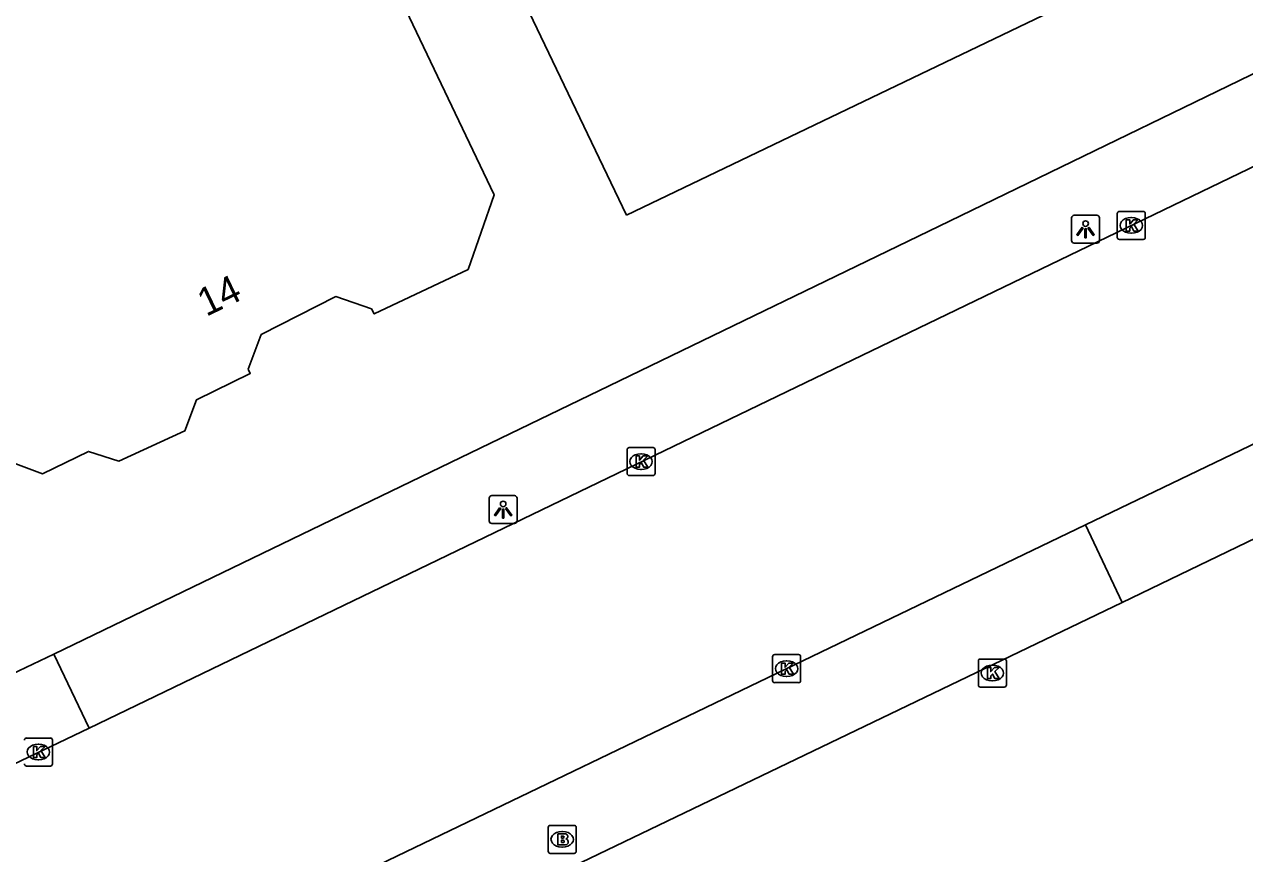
# Model space of a CAD drawing. Extents: x 157692 to 159670, y 381454 to 383289.
# Drawn here: x 158074.32 to 158117.92, y 381667.75 to 381697.36 of the extents above; entities that cross this region are included whole.
import ezdxf

# ---------------------------------------------------------------- set-up
doc = ezdxf.new("R2010")
doc.units = 0
for name, color, linetype in [('IMGEO_Brandkraan', 7, 'Continuous'), ('IMGEO_Kolk', 7, 'Continuous'), ('IMGEO_Lichtpunt', 7, 'Continuous'), ('IMGEO_Pand', 7, 'Continuous'), ('IMGEO_Pand_nummerreeks', 7, 'Continuous'), ('IMGEO_Rijbaan_lokaal_gesloten', 7, 'Continuous'), ('IMGEO_Voetpad_open', 7, 'Continuous')]:
    doc.layers.add(name, color=color, linetype=linetype)

msp = doc.modelspace()

# ---------------------------------------------------------------- linework, layer by layer
at = {"layer": 'IMGEO_Brandkraan'}
for p, q in [((158093.036, 381667.829), (158093.036, 381668.681)), ((158093.111, 381668.755), (158093.963, 381668.755)), ((158094.037, 381668.681), (158094.037, 381667.829)), ((158093.524, 381668.535), (158093.549, 381668.535)), ((158093.963, 381667.755), (158093.111, 381667.755)), ((158093.547, 381667.975), (158093.522, 381667.975))]:
    msp.add_line(p, q, dxfattribs=at)
for points in [[(158093.036, 381667.829), (158093.036, 381668.681)], [(158093.111, 381668.755), (158093.963, 381668.755)], [(158094.037, 381668.681), (158094.037, 381667.829)], [(158093.384, 381668.455), (158093.384, 381668.055), (158093.597, 381668.055)], [(158093.615, 381668.455), (158093.384, 381668.455)], [(158093.563, 381668.374), (158093.509, 381668.374), (158093.509, 381668.298)], [(158093.509, 381668.298), (158093.562, 381668.298)], [(158093.571, 381668.222), (158093.509, 381668.222), (158093.509, 381668.141)], [(158093.509, 381668.141), (158093.571, 381668.141)], [(158093.963, 381667.755), (158093.111, 381667.755)]]:
    msp.add_lwpolyline(points, dxfattribs=at)
for centre, radius, start, end in [((158093.113, 381668.679), 0.0765, 91.552, 178.448), ((158093.113, 381668.679), 0.0765, 91.552, 178.448), ((158093.961, 381668.679), 0.0765, 1.552, 88.448), ((158093.961, 381668.679), 0.0765, 1.552, 88.448), ((158093.564, 381668.336), 0.0379, 267.8285, 90.9355), ((158093.572, 381668.181), 0.0404, 269.8759, 90.5077), ((158093.619, 381668.31), 0.145, 59.4692, 91.5367), ((158093.644, 381668.357), 0.0922, 285.5137, 58.1501), ((158093.649, 381668.165), 0.105, 301.3115, 78.989), ((158093.113, 381667.831), 0.0765, 181.552, 268.448), ((158093.113, 381667.831), 0.0765, 181.552, 268.448), ((158093.603, 381668.306), 0.251, 268.6676, 293.5347), ((158093.961, 381667.831), 0.0765, 271.552, 358.448), ((158093.961, 381667.831), 0.0765, 271.552, 358.448)]:
    msp.add_arc(centre, radius, start, end, dxfattribs=at)
for centre, major_axis, ratio, start_param, end_param in [((158093.523, 381668.255), (-0.387, 0.002), 0.722429, 4.712389, 7.853982), ((158093.548, 381668.255), (-0.39, 0.002), 0.717154, 1.570796, 4.712389)]:
    msp.add_ellipse(centre, major_axis=major_axis, ratio=ratio, start_param=start_param, end_param=end_param, dxfattribs=at)
at = {"layer": 'IMGEO_Kolk'}
for p, q in [((158113.367, 381689.758), (158113.367, 381690.61)), ((158113.442, 381690.684), (158114.294, 381690.684)), ((158113.855, 381690.464), (158113.88, 381690.464)), ((158114.368, 381690.61), (158114.368, 381689.758)), ((158113.878, 381689.904), (158113.853, 381689.904)), ((158114.294, 381689.684), (158113.442, 381689.684)), ((158095.854, 381681.323), (158095.854, 381682.175)), ((158095.929, 381682.249), (158096.781, 381682.249)), ((158096.855, 381682.175), (158096.855, 381681.323)), ((158096.342, 381682.029), (158096.367, 381682.029)), ((158096.781, 381681.249), (158095.929, 381681.249)), ((158096.365, 381681.469), (158096.34, 381681.469)), ((158101.054, 381673.926), (158101.054, 381674.778)), ((158101.129, 381674.852), (158101.981, 381674.852)), ((158102.055, 381674.778), (158102.055, 381673.926)), ((158108.479, 381674.696), (158109.331, 381674.696)), ((158101.542, 381674.632), (158101.567, 381674.632)), ((158108.404, 381673.77), (158108.404, 381674.622)), ((158108.892, 381674.476), (158108.917, 381674.476)), ((158109.405, 381674.622), (158109.405, 381673.77)), ((158101.981, 381673.852), (158101.129, 381673.852)), ((158101.565, 381674.072), (158101.54, 381674.072)), ((158108.915, 381673.916), (158108.89, 381673.916)), ((158109.331, 381673.696), (158108.479, 381673.696)), ((158074.398, 381671.875), (158075.25, 381671.875)), ((158074.811, 381671.655), (158074.836, 381671.655)), ((158075.324, 381671.801), (158075.324, 381670.949)), ((158075.25, 381670.875), (158074.398, 381670.875)), ((158074.834, 381671.095), (158074.809, 381671.095))]:
    msp.add_line(p, q, dxfattribs=at)
for points in [[(158113.367, 381689.758), (158113.367, 381690.61)], [(158113.442, 381690.684), (158114.294, 381690.684)], [(158113.688, 381690.384), (158113.811, 381690.384), (158113.811, 381690.233), (158113.941, 381690.384), (158114.105, 381690.384), (158113.959, 381690.233), (158114.112, 381689.984), (158113.96, 381689.984), (158113.875, 381690.148), (158113.811, 381690.081), (158113.811, 381689.984), (158113.688, 381689.984), (158113.688, 381690.384)], [(158114.368, 381690.61), (158114.368, 381689.758)], [(158114.294, 381689.684), (158113.442, 381689.684)], [(158095.854, 381681.323), (158095.854, 381682.175)], [(158095.929, 381682.249), (158096.781, 381682.249)], [(158096.855, 381682.175), (158096.855, 381681.323)], [(158096.175, 381681.949), (158096.298, 381681.949), (158096.298, 381681.798), (158096.428, 381681.949), (158096.592, 381681.949), (158096.446, 381681.798), (158096.599, 381681.549), (158096.447, 381681.549), (158096.362, 381681.713), (158096.298, 381681.646), (158096.298, 381681.549), (158096.175, 381681.549), (158096.175, 381681.949)], [(158096.781, 381681.249), (158095.929, 381681.249)], [(158101.054, 381673.926), (158101.054, 381674.778)], [(158101.129, 381674.852), (158101.981, 381674.852)], [(158102.055, 381674.778), (158102.055, 381673.926)], [(158108.479, 381674.696), (158109.331, 381674.696)], [(158101.375, 381674.552), (158101.498, 381674.552), (158101.498, 381674.401), (158101.628, 381674.552), (158101.792, 381674.552), (158101.646, 381674.401), (158101.799, 381674.152), (158101.647, 381674.152), (158101.562, 381674.316), (158101.498, 381674.249), (158101.498, 381674.152), (158101.375, 381674.152), (158101.375, 381674.552)], [(158108.404, 381673.77), (158108.404, 381674.622)], [(158108.725, 381674.396), (158108.848, 381674.396), (158108.848, 381674.245), (158108.978, 381674.396), (158109.142, 381674.396), (158108.996, 381674.245), (158109.149, 381673.996), (158108.997, 381673.996), (158108.912, 381674.16), (158108.848, 381674.093), (158108.848, 381673.996), (158108.725, 381673.996), (158108.725, 381674.396)], [(158109.405, 381674.622), (158109.405, 381673.77)], [(158101.981, 381673.852), (158101.129, 381673.852)], [(158109.331, 381673.696), (158108.479, 381673.696)], [(158074.398, 381671.875), (158075.25, 381671.875)], [(158075.324, 381671.801), (158075.324, 381670.949)], [(158074.644, 381671.575), (158074.767, 381671.575), (158074.767, 381671.424), (158074.897, 381671.575), (158075.061, 381671.575), (158074.915, 381671.424), (158075.068, 381671.175), (158074.916, 381671.175), (158074.831, 381671.339), (158074.767, 381671.272), (158074.767, 381671.175), (158074.644, 381671.175), (158074.644, 381671.575)], [(158075.25, 381670.875), (158074.398, 381670.875)]]:
    msp.add_lwpolyline(points, dxfattribs=at)
for centre, start, end in [((158113.444, 381690.608), 91.552, 178.448), ((158113.444, 381690.608), 91.552, 178.448), ((158114.292, 381690.608), 1.552, 88.448), ((158114.292, 381690.608), 1.552, 88.448), ((158113.444, 381689.76), 181.552, 268.448), ((158113.444, 381689.76), 181.552, 268.448), ((158114.292, 381689.76), 271.552, 358.448), ((158114.292, 381689.76), 271.552, 358.448), ((158095.931, 381682.173), 91.552, 178.448), ((158095.931, 381682.173), 91.552, 178.448), ((158096.779, 381682.173), 1.552, 88.448), ((158096.779, 381682.173), 1.552, 88.448), ((158095.931, 381681.325), 181.552, 268.448), ((158095.931, 381681.325), 181.552, 268.448), ((158096.779, 381681.325), 271.552, 358.448), ((158096.779, 381681.325), 271.552, 358.448), ((158101.131, 381674.776), 91.552, 178.448), ((158101.131, 381674.776), 91.552, 178.448), ((158101.979, 381674.776), 1.552, 88.448), ((158101.979, 381674.776), 1.552, 88.448), ((158108.481, 381674.62), 91.552, 178.448), ((158108.481, 381674.62), 91.552, 178.448), ((158109.329, 381674.62), 1.552, 88.448), ((158109.329, 381674.62), 1.552, 88.448), ((158101.131, 381673.928), 181.552, 268.448), ((158101.131, 381673.928), 181.552, 268.448), ((158101.979, 381673.928), 271.552, 358.448), ((158101.979, 381673.928), 271.552, 358.448), ((158108.481, 381673.772), 181.552, 268.448), ((158108.481, 381673.772), 181.552, 268.448), ((158109.329, 381673.772), 271.552, 358.448), ((158109.329, 381673.772), 271.552, 358.448), ((158074.4, 381671.799), 91.552, 178.448), ((158074.4, 381671.799), 91.552, 178.448), ((158075.248, 381671.799), 1.552, 88.448), ((158075.248, 381671.799), 1.552, 88.448), ((158074.4, 381670.951), 181.552, 268.448), ((158074.4, 381670.951), 181.552, 268.448), ((158075.248, 381670.951), 271.552, 358.448), ((158075.248, 381670.951), 271.552, 358.448)]:
    msp.add_arc(centre, 0.0765, start, end, dxfattribs=at)
for centre, major_axis, ratio, start_param, end_param in [((158113.854, 381690.184), (-0.387, 0.002), 0.722429, 4.712389, 7.853982), ((158113.879, 381690.184), (-0.39, 0.002), 0.717154, 1.570796, 4.712389), ((158096.341, 381681.749), (-0.387, 0.002), 0.722429, 4.712389, 7.853982), ((158096.366, 381681.749), (-0.39, 0.002), 0.717154, 1.570796, 4.712389), ((158101.541, 381674.352), (-0.387, 0.002), 0.722429, 4.712389, 7.853982), ((158101.566, 381674.352), (-0.39, 0.002), 0.717154, 1.570796, 4.712389), ((158108.891, 381674.196), (-0.387, 0.002), 0.722429, 4.712389, 7.853982), ((158108.916, 381674.196), (-0.39, 0.002), 0.717154, 1.570796, 4.712389), ((158074.81, 381671.375), (-0.387, 0.002), 0.722429, 4.712389, 7.853982), ((158074.835, 381671.375), (-0.39, 0.002), 0.717154, 1.570796, 4.712389)]:
    msp.add_ellipse(centre, major_axis=major_axis, ratio=ratio, start_param=start_param, end_param=end_param, dxfattribs=at)
at = {"layer": 'IMGEO_Lichtpunt'}
for p, q in [((158111.735, 381690.452), (158111.735, 381689.645)), ((158111.735, 381690.452), (158111.735, 381689.645)), ((158112.637, 381690.547), (158111.829, 381690.547)), ((158112.637, 381690.547), (158111.829, 381690.547)), ((158112.731, 381689.645), (158112.731, 381690.452)), ((158112.731, 381689.645), (158112.731, 381690.452)), ((158111.829, 381689.551), (158112.637, 381689.551)), ((158111.829, 381689.551), (158112.637, 381689.551)), ((158090.928, 381680.438), (158090.928, 381679.631)), ((158090.928, 381680.438), (158090.928, 381679.631)), ((158091.83, 381680.533), (158091.022, 381680.533)), ((158091.83, 381680.533), (158091.022, 381680.533)), ((158091.924, 381679.631), (158091.924, 381680.438)), ((158091.924, 381679.631), (158091.924, 381680.438)), ((158091.022, 381679.537), (158091.83, 381679.537)), ((158091.022, 381679.537), (158091.83, 381679.537))]:
    msp.add_line(p, q, dxfattribs=at)
for points in [[(158112.109, 381690.116), (158112.148, 381690.088), (158111.96, 381689.826), (158111.922, 381689.853), (158112.109, 381690.116)], [(158112.211, 381690.068), (158112.258, 381690.068), (158112.258, 381689.746), (158112.211, 381689.746), (158112.211, 381690.068)], [(158112.321, 381690.088), (158112.359, 381690.115), (158112.546, 381689.853), (158112.507, 381689.825), (158112.321, 381690.088)], [(158091.302, 381680.102), (158091.341, 381680.074), (158091.153, 381679.812), (158091.115, 381679.839), (158091.302, 381680.102)], [(158091.404, 381680.054), (158091.451, 381680.054), (158091.451, 381679.732), (158091.404, 381679.732), (158091.404, 381680.054)], [(158091.514, 381680.074), (158091.552, 381680.101), (158091.739, 381679.839), (158091.7, 381679.811), (158091.514, 381680.074)]]:
    msp.add_lwpolyline(points, dxfattribs=at)
for centre in [(158112.234, 381690.25), (158091.427, 381680.236)]:
    msp.add_circle(centre, 0.0994, dxfattribs=at)
for centre, start, end in [((158111.829, 381690.452), 90, 180), ((158111.829, 381690.452), 90, 180), ((158112.637, 381690.452), 0, 90), ((158112.637, 381690.452), 0, 90), ((158111.829, 381689.645), 180, 270), ((158111.829, 381689.645), 180, 270), ((158112.637, 381689.645), 270, 0), ((158112.637, 381689.645), 270, 360), ((158091.022, 381680.438), 90, 180), ((158091.022, 381680.438), 90, 180), ((158091.83, 381680.438), 0, 90), ((158091.83, 381680.438), 0, 90), ((158091.022, 381679.631), 180, 270), ((158091.022, 381679.631), 180, 270), ((158091.83, 381679.631), 270, 0), ((158091.83, 381679.631), 270, 360)]:
    msp.add_arc(centre, 0.0946, start, end, dxfattribs=at)
at = {"layer": 'IMGEO_Pand'}
for points in [[(158082.315, 381685.049), (158082.781, 381686.285), (158085.446, 381687.641), (158086.722, 381687.201), (158086.823, 381687.022), (158090.172, 381688.615), (158091.103, 381691.273), (158087.956, 381697.889), (158090.593, 381699.145), (158075.432, 381730.662), (158070.933, 381728.483)], [(158095.837, 381690.555), (158117.435, 381700.917), (158114.941, 381703.211), (158107.496, 381718.594), (158087.076, 381708.818), (158095.837, 381690.555)], [(158072.255, 381682.327), (158074.971, 381681.307), (158076.614, 381682.114), (158077.694, 381681.766), (158080.056, 381682.847), (158080.468, 381683.952), (158082.39, 381684.9), (158082.315, 381685.049)]]:
    msp.add_lwpolyline(points, dxfattribs=at)
at = {"layer": 'IMGEO_Rijbaan_lokaal_gesloten'}
for points in [[(158076.639, 381672.23), (158120.418, 381693.339), (158122.546, 381694.375)], [(158118.396, 381682.456), (158112.226, 381679.488)], [(158112.226, 381679.488), (158076.593, 381662.346)], [(158070.922, 381669.494), (158076.639, 381672.23)]]:
    msp.add_lwpolyline(points, dxfattribs=at)
at = {"layer": 'IMGEO_Voetpad_open'}
for points in [[(158122.884, 381701.311), (158121.318, 381697.1), (158107.373, 381690.341), (158095.213, 381684.451), (158075.377, 381674.875)], [(158112.226, 381679.488), (158113.537, 381676.714)], [(158119.708, 381679.687), (158113.537, 381676.714)], [(158113.537, 381676.714), (158077.956, 381659.612)], [(158075.377, 381674.875), (158069.612, 381672.132)], [(158075.377, 381674.875), (158076.639, 381672.23)]]:
    msp.add_lwpolyline(points, dxfattribs=at)

# ---------------------------------------------------------------- texts
at = {"layer": 'IMGEO_Pand_nummerreeks'}
msp.add_text('14', height=1, rotation=25.6763, dxfattribs=at).set_placement((158080.817, 381686.914))

doc.saveas('drawing.dxf')
